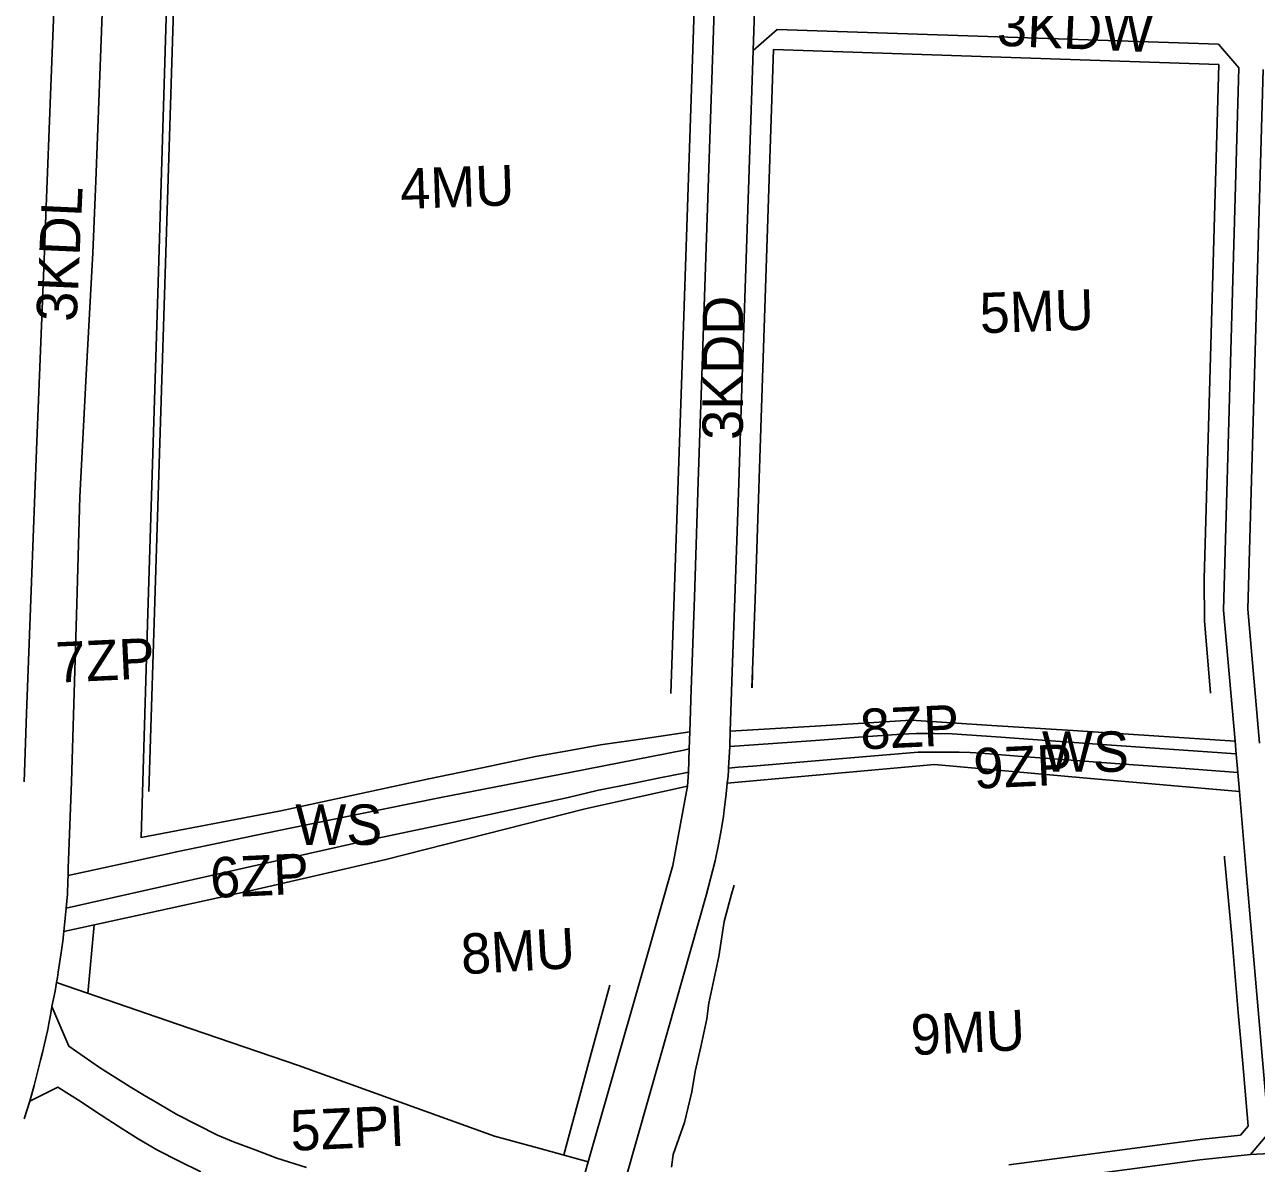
# Model space of a CAD drawing. Extents: x 7418021 to 7419743, y 5540231 to 5541685.
# Drawn here: x 7418764.3 to 7419069.1, y 5540508.6 to 5540790.3 of the extents above; entities that cross this region are included whole.
import ezdxf

# ---------------------------------------------------------------- set-up
doc = ezdxf.new("R2010")
doc.units = 0
for name, color, linetype in [('linie_rozgraniczajace', 7, 'Continuous'), ('linie_zabudowy_nieprzekraczalne', 7, 'Continuous'), ('oznaczenia_przeznaczen', 7, 'Continuous')]:
    doc.layers.add(name, color=color, linetype=linetype)

msp = doc.modelspace()

# ---------------------------------------------------------------- linework, layer by layer
at = {"layer": 'linie_rozgraniczajace'}
for points in [[(7418814.14, 5541027.22), (7418796.31, 5541007.56), (7418794.05, 5541004.64), (7418789.12, 5540998.29), (7418786.91, 5540992.85), (7418784.7, 5540987.42), (7418781.71, 5540978.85), (7418780.09, 5540971.46), (7418778.47, 5540964.06), (7418777.62, 5540953.12), (7418776.5, 5540923.73), (7418775.38, 5540894.35), (7418773.52, 5540846.17), (7418771.67, 5540797.99), (7418770.78, 5540775.04), (7418769.55, 5540743.2), (7418769.21, 5540734.31), (7418767.27, 5540685.15), (7418766.02, 5540652.51), (7418764.77, 5540619.88), (7418764.16, 5540602.99)], [(7418770.78, 5540775.04), (7418771.67, 5540797.99), (7418773.52, 5540846.17), (7418775.38, 5540894.35), (7418776.5, 5540923.73), (7418777.62, 5540953.12), (7418778.47, 5540964.06), (7418780.09, 5540971.46), (7418781.71, 5540978.85), (7418784.7, 5540987.42), (7418786.91, 5540992.85), (7418789.12, 5540998.29), (7418794.05, 5541004.64)], [(7418799.68, 5540802.96), (7418797.25, 5540723.86), (7418794.83, 5540644.76), (7418793.97, 5540616.99), (7418793.11, 5540589.21), (7418827.68, 5540595.79), (7418845.99, 5540599.77), (7418864.3, 5540603.76), (7418877.49, 5540606.5), (7418890.67, 5540609.25), (7418898.73, 5540610.69), (7418906.79, 5540612.14), (7418917.84, 5540613.74), (7418928.89, 5540615.34), (7418928.75, 5540611.14), (7418928.07, 5540610.99), (7418927.39, 5540610.84), (7418899.63, 5540605.43), (7418867.3, 5540599.1), (7418846.49, 5540594.91), (7418821.15, 5540589.75), (7418809.45, 5540587.27), (7418802.28, 5540585.74), (7418790.7, 5540583.22), (7418775.05, 5540579.84), (7418775.11, 5540581.83), (7418775.19, 5540583.65), (7418775.91, 5540602.98), (7418777.25, 5540647.02), (7418777.95, 5540673.54), (7418779.57, 5540703.69), (7418781.2, 5540733.85), (7418781.89, 5540751.62), (7418783.66, 5540797.53)], [(7418934.93, 5540793.8), (7418933.44, 5540749.87), (7418931.96, 5540705.93), (7418930.99, 5540677.32), (7418930.02, 5540648.72), (7418929.25, 5540625.82), (7418928.89, 5540615.34), (7418917.84, 5540613.74), (7418906.79, 5540612.14), (7418898.73, 5540610.69), (7418890.67, 5540609.25), (7418877.49, 5540606.5), (7418864.3, 5540603.76), (7418845.99, 5540599.77), (7418827.68, 5540595.79), (7418793.11, 5540589.21), (7418793.97, 5540616.99), (7418794.83, 5540644.76), (7418797.25, 5540723.86), (7418799.68, 5540802.96)], [(7418945.18, 5540800.98), (7418944.6, 5540783.96), (7418943.44, 5540749.53), (7418941.95, 5540705.6), (7418940.98, 5540676.99), (7418940.02, 5540648.38), (7418939.4, 5540630.2), (7418938.9, 5540615.51), (7418938.79, 5540612.02), (7418938.77, 5540611.76), (7418938.49, 5540606.4), (7418938.44, 5540605.78), (7418938.34, 5540604.43), (7418938.17, 5540602.64), (7418938, 5540600.85), (7418937.82, 5540599.28), (7418937.41, 5540596.09), (7418937.19, 5540594.46), (7418936.64, 5540591.04), (7418936.07, 5540587.9), (7418935.14, 5540583.49), (7418932.97, 5540574.89), (7418921.59, 5540534.82), (7418910.2, 5540494.76)], [(7419083.62, 5540511.65), (7419067.63, 5540510.82), (7419072.18, 5540516.17), (7419066.58, 5540580.83), (7419064.86, 5540600.6), (7419064.45, 5540605.34), (7419064.06, 5540609.88), (7419063.78, 5540613.08), (7419060.97, 5540645.49), (7419062.86, 5540712.57), (7419064.76, 5540779.65), (7419059.66, 5540785.52), (7419005.08, 5540787.34), (7418950.51, 5540789.17), (7418944.6, 5540783.96), (7418945.18, 5540800.98)], [(7418783.66, 5540797.53), (7418781.89, 5540751.62), (7418781.2, 5540733.85), (7418779.57, 5540703.69), (7418777.95, 5540673.54), (7418777.25, 5540647.02), (7418775.91, 5540602.98), (7418775.19, 5540583.65), (7418775.11, 5540581.83), (7418775.05, 5540579.84), (7418775.01, 5540578.51), (7418774.91, 5540575.18), (7418774.6, 5540571.78), (7418774, 5540565.99), (7418773.72, 5540563.58), (7418773.5, 5540561.87), (7418773.27, 5540560.16), (7418772.96, 5540558.03), (7418772.64, 5540555.91), (7418772.43, 5540554.61), (7418772.22, 5540553.32), (7418771.87, 5540551.24), (7418771.48, 5540549.34), (7418771.08, 5540547.45), (7418770.7, 5540545.31), (7418770.32, 5540543.17), (7418770.01, 5540541.73), (7418769.7, 5540540.3), (7418769.21, 5540538.17), (7418768.72, 5540536.04), (7418768.25, 5540534.1), (7418767.77, 5540532.16), (7418766.64, 5540527.91), (7418765.59, 5540523.96), (7418764.22, 5540519.61)], [(7418899.99, 5540495.81), (7418903.76, 5540509), (7418908.96, 5540527.16), (7418917.92, 5540558.51), (7418921.3, 5540570.4), (7418924.68, 5540582.3), (7418926.58, 5540592.61), (7418928.29, 5540601.95), (7418928.55, 5540605.34), (7418928.75, 5540611.14), (7418928.89, 5540615.34), (7418929.25, 5540625.82), (7418930.02, 5540648.72), (7418930.99, 5540677.32), (7418931.96, 5540705.93), (7418933.44, 5540749.87), (7418934.93, 5540793.8)], [(7419070.75, 5540779.22), (7419068.86, 5540712.48), (7419066.98, 5540645.75), (7419069.85, 5540612.59)], [(7419069.85, 5540612.59), (7419066.98, 5540645.75), (7419068.86, 5540712.48), (7419070.75, 5540779.22)], [(7418764.16, 5540602.99), (7418764.77, 5540619.88), (7418766.02, 5540652.51), (7418767.27, 5540685.15), (7418769.21, 5540734.31), (7418769.55, 5540743.2), (7418770.78, 5540775.04)], [(7418834.07, 5540507.61), (7418826.7, 5540509.9), (7418821.33, 5540511.93), (7418815.95, 5540513.96), (7418812.06, 5540515.57), (7418807.02, 5540518.12), (7418801.98, 5540520.67), (7418799.74, 5540521.99), (7418797.5, 5540523.3), (7418793.96, 5540525.43), (7418790.42, 5540527.56), (7418786.62, 5540529.93), (7418782.81, 5540532.3), (7418779.04, 5540534.93), (7418775.28, 5540537.56), (7418771.08, 5540547.45), (7418771.48, 5540549.34), (7418771.87, 5540551.24), (7418772.22, 5540553.32), (7418802.13, 5540543.05), (7418832.03, 5540532.78), (7418856.29, 5540524.06), (7418880.54, 5540515.33), (7418892.15, 5540512.17), (7418903.76, 5540509), (7418899.99, 5540495.81)], [(7418788.64, 5540517.09), (7418784.9, 5540519.47), (7418781.61, 5540521.64), (7418778.32, 5540523.81), (7418775.42, 5540525.62), (7418772.51, 5540527.43), (7418769.05, 5540525.7), (7418765.59, 5540523.96), (7418766.64, 5540527.91), (7418767.77, 5540532.16), (7418768.25, 5540534.1), (7418768.72, 5540536.04), (7418769.21, 5540538.17), (7418769.7, 5540540.3), (7418770.01, 5540541.73), (7418770.32, 5540543.17), (7418770.7, 5540545.31), (7418771.08, 5540547.45), (7418775.28, 5540537.56), (7418779.04, 5540534.93), (7418782.81, 5540532.3), (7418786.62, 5540529.93), (7418790.42, 5540527.56), (7418793.96, 5540525.43), (7418797.5, 5540523.3), (7418799.74, 5540521.99), (7418801.98, 5540520.67), (7418807.02, 5540518.12), (7418812.06, 5540515.57), (7418815.95, 5540513.96), (7418821.33, 5540511.93), (7418826.7, 5540509.9), (7418834.07, 5540507.61)], [(7418764.22, 5540519.61), (7418765.59, 5540523.96), (7418769.05, 5540525.7), (7418772.51, 5540527.43), (7418775.42, 5540525.62), (7418778.32, 5540523.81), (7418781.61, 5540521.64), (7418784.9, 5540519.47), (7418788.64, 5540517.09), (7418792.39, 5540514.71), (7418794.79, 5540513.3), (7418797.19, 5540511.89), (7418802.54, 5540509.18), (7418807.88, 5540506.48)], [(7418807.88, 5540506.48), (7418802.54, 5540509.18), (7418797.19, 5540511.89), (7418794.79, 5540513.3), (7418792.39, 5540514.71), (7418788.64, 5540517.09)], [(7418984.43, 5540500.04), (7419055.07, 5540509.46), (7419067.63, 5540510.82), (7419083.62, 5540511.65)]]:
    msp.add_lwpolyline(points, dxfattribs=at)
for points in [[(7418944.6, 5540783.96), (7418950.51, 5540789.17), (7419005.08, 5540787.34), (7419059.66, 5540785.52), (7419064.76, 5540779.65), (7419062.86, 5540712.57), (7419060.97, 5540645.49), (7419063.78, 5540613.08), (7419043.71, 5540614.37), (7419023.63, 5540615.66), (7419003.63, 5540616.94), (7418983.63, 5540618.23), (7418961.27, 5540616.87), (7418938.9, 5540615.51), (7418939.4, 5540630.2), (7418940.02, 5540648.38), (7418940.98, 5540676.99), (7418941.95, 5540705.6), (7418943.44, 5540749.53)], [(7418938.9, 5540615.51), (7418961.27, 5540616.87), (7418983.63, 5540618.23), (7419003.63, 5540616.94), (7419023.63, 5540615.66), (7419043.71, 5540614.37), (7419063.78, 5540613.08), (7419064.06, 5540609.88), (7419064, 5540609.89), (7419060.49, 5540610.14), (7419051.04, 5540610.81), (7419041.59, 5540611.48), (7419028.53, 5540612.41), (7419004.65, 5540614.1), (7418993.83, 5540614.87), (7418989.37, 5540614.93), (7418984.92, 5540614.99), (7418983.09, 5540614.89), (7418981.26, 5540614.8), (7418970.64, 5540614.03), (7418960.01, 5540613.25), (7418949.39, 5540612.51), (7418938.77, 5540611.76), (7418938.79, 5540612.02)], [(7418938.77, 5540611.76), (7418949.39, 5540612.51), (7418960.01, 5540613.25), (7418970.64, 5540614.03), (7418981.26, 5540614.8), (7418983.09, 5540614.89), (7418984.92, 5540614.99), (7418989.37, 5540614.93), (7418993.83, 5540614.87), (7419004.65, 5540614.1), (7419028.53, 5540612.41), (7419041.59, 5540611.48), (7419051.04, 5540610.81), (7419060.49, 5540610.14), (7419064, 5540609.89), (7419064.06, 5540609.88), (7419064.45, 5540605.34), (7419050.4, 5540606.35), (7419036.35, 5540607.36), (7419029.78, 5540607.86), (7419023.22, 5540608.37), (7419012.11, 5540609.22), (7419001.01, 5540610.08), (7418998.28, 5540610.23), (7418995.54, 5540610.38), (7418994.27, 5540610.37), (7418993, 5540610.37), (7418989.19, 5540610.35), (7418985.39, 5540610.33), (7418966.72, 5540608.76), (7418944.46, 5540606.89), (7418940.86, 5540606.6), (7418938.49, 5540606.4)], [(7418928.75, 5540611.14), (7418928.55, 5540605.34), (7418928.2, 5540605.31), (7418924.83, 5540604.65), (7418921.46, 5540603.98), (7418915.16, 5540602.71), (7418905.94, 5540600.82), (7418898.83, 5540599.15), (7418884.69, 5540596.1), (7418870.54, 5540593.06), (7418849.73, 5540588.69), (7418834.3, 5540585.22), (7418818.88, 5540581.75), (7418800.95, 5540577.71), (7418783.02, 5540573.67), (7418774.6, 5540571.78), (7418774.91, 5540575.18), (7418775.01, 5540578.51), (7418775.05, 5540579.84), (7418790.7, 5540583.22), (7418802.28, 5540585.74), (7418809.45, 5540587.27), (7418821.15, 5540589.75), (7418846.49, 5540594.91), (7418867.3, 5540599.1), (7418899.63, 5540605.43), (7418927.39, 5540610.84), (7418928.07, 5540610.99)], [(7418938.49, 5540606.4), (7418940.86, 5540606.6), (7418944.46, 5540606.89), (7418966.72, 5540608.76), (7418985.39, 5540610.33), (7418989.19, 5540610.35), (7418993, 5540610.37), (7418994.27, 5540610.37), (7418995.54, 5540610.38), (7418998.28, 5540610.23), (7419001.01, 5540610.08), (7419012.11, 5540609.22), (7419023.22, 5540608.37), (7419029.78, 5540607.86), (7419036.35, 5540607.36), (7419050.4, 5540606.35), (7419064.45, 5540605.34), (7419064.86, 5540600.6), (7419027.14, 5540603.92), (7418989.41, 5540607.25), (7418963.79, 5540604.94), (7418938.17, 5540602.64), (7418938.34, 5540604.43), (7418938.44, 5540605.78)], [(7418928.55, 5540605.34), (7418928.29, 5540601.95), (7418915.65, 5540599.14), (7418903.01, 5540596.34), (7418878.34, 5540590.05), (7418853.68, 5540583.76), (7418837.23, 5540579.97), (7418820.79, 5540576.19), (7418797.39, 5540571.09), (7418774, 5540565.99), (7418774.6, 5540571.78), (7418783.02, 5540573.67), (7418800.95, 5540577.71), (7418818.88, 5540581.75), (7418834.3, 5540585.22), (7418849.73, 5540588.69), (7418870.54, 5540593.06), (7418884.69, 5540596.1), (7418898.83, 5540599.15), (7418905.94, 5540600.82), (7418915.16, 5540602.71), (7418921.46, 5540603.98), (7418924.83, 5540604.65), (7418928.2, 5540605.31)], [(7418938.17, 5540602.64), (7418963.79, 5540604.94), (7418989.41, 5540607.25), (7419027.14, 5540603.92), (7419064.86, 5540600.6), (7419066.58, 5540580.83), (7419072.18, 5540516.17), (7419067.63, 5540510.82), (7419055.07, 5540509.46), (7418984.43, 5540500.04), (7418913.79, 5540490.61), (7418910.2, 5540494.76), (7418921.59, 5540534.82), (7418932.97, 5540574.89), (7418935.14, 5540583.49), (7418936.07, 5540587.9), (7418936.64, 5540591.04), (7418937.19, 5540594.46), (7418937.41, 5540596.09), (7418937.82, 5540599.28), (7418938, 5540600.85)], [(7418928.29, 5540601.95), (7418926.58, 5540592.61), (7418924.68, 5540582.3), (7418921.3, 5540570.4), (7418917.92, 5540558.51), (7418908.96, 5540527.16), (7418903.76, 5540509), (7418892.15, 5540512.17), (7418880.54, 5540515.33), (7418856.29, 5540524.06), (7418832.03, 5540532.78), (7418802.13, 5540543.05), (7418772.22, 5540553.32), (7418772.43, 5540554.61), (7418772.64, 5540555.91), (7418772.96, 5540558.03), (7418773.27, 5540560.16), (7418773.5, 5540561.87), (7418773.72, 5540563.58), (7418774, 5540565.99), (7418797.39, 5540571.09), (7418820.79, 5540576.19), (7418837.23, 5540579.97), (7418853.68, 5540583.76), (7418878.34, 5540590.05), (7418903.01, 5540596.34), (7418915.65, 5540599.14)]]:
    msp.add_lwpolyline(points, close=True, dxfattribs=at)
at = {"layer": 'linie_zabudowy_nieprzekraczalne'}
for points in [[(7418802.06, 5540822.84), (7418795.06, 5540600.62)], [(7418926.96, 5540706.11), (7418929.93, 5540793.97)], [(7418949.61, 5540784.2), (7418946.95, 5540705.43)], [(7419059.78, 5540780.51), (7418949.61, 5540784.2)], [(7419056.19, 5540653.22), (7419059.78, 5540780.51)], [(7418925.03, 5540648.89), (7418926.96, 5540706.11)], [(7418946.95, 5540705.43), (7418945.02, 5540648.21)], [(7419056.2, 5540642.75), (7419056.19, 5540653.22)], [(7418924.21, 5540624.84), (7418925.03, 5540648.89)], [(7418945.02, 5540648.21), (7418944.27, 5540626.28)], [(7419057.74, 5540625), (7419056.2, 5540642.75)], [(7418944.4, 5540630.03), (7418944.28, 5540626.36)], [(7419057.74, 5540624.92), (7419057.74, 5540625)], [(7419061.2, 5540584.2), (7419061.18, 5540584.65)], [(7419062.96, 5540564.75), (7419061.2, 5540584.2)], [(7418939.89, 5540577.47), (7418939.19, 5540575.18)], [(7418939.19, 5540575.18), (7418937.38, 5540568.45)], [(7418937.38, 5540568.45), (7418936.08, 5540559.76)], [(7418781.51, 5540567.63), (7418779.96, 5540550.66)], [(7419064.59, 5540545.89), (7419062.96, 5540564.75)], [(7418936.08, 5540559.76), (7418933.56, 5540548.28)], [(7418904.51, 5540535.75), (7418909.07, 5540552.66)], [(7418933.56, 5540548.28), (7418933.12, 5540544.33)], [(7418933.12, 5540544.33), (7418931.65, 5540537.46)], [(7419065.61, 5540534.19), (7419064.59, 5540545.89)], [(7418931.65, 5540537.46), (7418930.2, 5540531.37)], [(7418897.74, 5540510.69), (7418904.51, 5540535.75)], [(7418930.2, 5540531.37), (7418929.42, 5540526.3)], [(7419067.02, 5540517.83), (7419065.61, 5540534.19)], [(7418929.42, 5540526.3), (7418927.58, 5540518.68)], [(7418927.58, 5540518.68), (7418924.75, 5540510.77)], [(7419065.13, 5540515.6), (7419067.02, 5540517.83)], [(7419029.1, 5540511.04), (7419045.72, 5540513.26)], [(7419045.72, 5540513.26), (7419055.79, 5540514.59)], [(7419055.79, 5540514.59), (7419065.13, 5540515.6)], [(7418924.75, 5540510.77), (7418924.37, 5540507.64)], [(7419007.86, 5540508.21), (7419029.1, 5540511.04)]]:
    msp.add_lwpolyline(points, dxfattribs=at)

# ---------------------------------------------------------------- texts
at = {"layer": 'oznaczenia_przeznaczen'}
for s, rotation, p in [('3KDW', 357.5522, (7419004.76, 5540785.15)), ('4MU', 1.9767, (7418857.4, 5540744.71)), ('3KDL', 87.417, (7418777.17, 5540716.7)), ('5MU', 1.9767, (7419000.77, 5540713.96)), ('3KDD', 89.9102, (7418942.01, 5540687.59)), ('7ZP', 2.669, (7418772.21, 5540627.52)), ('8ZP', 2.669, (7418971.28, 5540610.99)), ('9ZP', 2.669, (7418999.31, 5540601.27)), ('6ZP', 2.669, (7418810.42, 5540574.25)), ('8MU', 3.2408, (7418872.53, 5540555.36)), ('9MU', 2.669, (7418983.81, 5540535.36)), ('5ZPI', 2.669, (7418830.28, 5540511.68))]:
    msp.add_text(s, height=10, rotation=rotation, dxfattribs=at).set_placement(p)
for p in [(7419016.01, 5540605.48), (7418831.27, 5540587.4)]:
    msp.add_text('WS', height=10, dxfattribs=at).set_placement(p)

doc.saveas('drawing.dxf')
